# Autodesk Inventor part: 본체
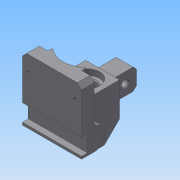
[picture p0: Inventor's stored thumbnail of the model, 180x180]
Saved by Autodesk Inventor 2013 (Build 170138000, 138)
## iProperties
Created: 2016-11
Part Number: 본체
Material: 일반
Document SubType Name: Modeling
Designer: Administrator
Density: 1 g/cm^3
Author: Administrator
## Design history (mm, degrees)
sketch "스케치4"
  geometry: L1 (18, -11)-(0, -29); L2 (0, -29)-(-26, -29); L3 (-30, -25)-(-30, 29); L4 (-30, 29)-(18, 29); L5 (18, 29)-(18, -11); L6 (0, -29)-(0, 29); L7 (-26, -29)-(-30, -25); 3 further points
  constraints: 14 end point, 3 point on line, 2 vertical, 1 coincident, 1 horizontal, 1 midpoint, 1 parallel, 1 perpendicular
  dimensions: "d4" = 45 deg angle of L2 L1; "d5" = 58 distance between parallel lines of L2 L4; "d6" = 48 distance between parallel lines of L3 L5; "d8" = 30 distance from line of L3 L1.end; "d9" = 4 distance of L2.end point (-30, -29); "d10" = 4 distance of L3.start point (-30, -29) (= d9)
extrude "돌출1" new body sketch "스케치4" stored distance "d11" = 40; taper "d12" = 0 deg
sketch "스케치5"
  geometry: L1 (18, 29)-(18, -11) reference; L2 (18, -11)-(0, -29) reference; L3 (0, -29)-(-26, -29) reference; L4 (-26, -29)-(-30, -25) reference; L5 (-30, -25)-(-30, 29) reference; L6 (-30, 29)-(18, 29) reference; L7 (-27, -15)-(-42, -15); L8 (-42, 61)-(-27, 61); L9 (-27, 15.292)-(-27, 61); L10 (-35, -12)-(-42, -12); L11 (-35, -12)-(-35, 8); L12 (-35, 8)-(-42, 8); L13 (-42, -15)-(-42, -12); L14 (-42, 8)-(-42, 61); A1 r 13 centre (-27, -2) between (-27, -15) and (-23.389, 10.488); A2 r 5 centre (-22, 15.292) between (-27, 15.292) and (-23.389, 10.488); 2 further points
  constraints: 16 end point, 5 point on circle, 4 perpendicular, 3 point on line, 3 tangent, 2 centre point, 2 parallel, 1 horizontal
  dimensions: "d19" = 90 distance between parallel lines of L8 L3; "d21" = 26 diameter of A1; "d22" = 63 distance from line of L8 A1.centre; "d23" = 3 distance between parallel lines of L7 L10; "d25" = 20 distance of L10.start L11.end; "d26" = 60 distance between parallel lines of L1 L14; "d27" = 15 distance between parallel lines of L14 L9; "d28" = 7 distance between parallel lines of L13 L11; "d29" = 5 radius of A2
extrude "돌출2" join sketch "스케치5" stored distance "d30" = 70; taper "d31" = 0 deg
sketch "스케치6"
  geometry: L1 (0, -45)-(40, -45) reference; L2 (0, -45)-(0, 0) reference; L3 (0, -40)-(40, -40); L4 (40, -40)-(40, -45); L5 (40, -45)-(0, -45); L6 (0, -45)-(0, -40); 2 further points
  constraints: 8 end point, 2 midpoint, 2 parallel, 1 collinear, 1 horizontal, 1 perpendicular
  dimensions: "d32" = 5 distance of L5.end L3.start
extrude "돌출3" join sketch "스케치6" stored distance "d34" = 10; taper "d35" = 0 deg
sketch "스케치7"
  geometry: L1 (0, 0)-(70, 0) reference; L2 (0, 0)-(0, 15) reference; L3 (0, 15)-(15, 15) reference; L4 (15, 15)-(15, 20) reference; L5 (15, 20)-(55, 20) reference; L6 (55, 20)-(55, 15) reference; L7 (55, 15)-(70, 15) reference; L8 (70, 15)-(70, 0) reference; L9 (70, 0)-(0, 0) reference; C1 r 29 at (35, 42); 2 further points
  constraints: 1 centre point, 1 midpoint, 1 vertical alignment
  dimensions: "d36" = 58 diameter of C1; "d37" = 42 distance from line of L1 C1.centre
extrude "돌출4" cut sketch "스케치7" distance "d38" = 18; taper "d39" = 0 deg
sketch "스케치8"
  geometry: L1 (0, -29)-(-26, -29) reference; L2 (-26, -29)-(-30, -25) reference; L3 (-30, -25)-(-30, -15) reference; L4 (-30, -15)-(-42, -15) reference; L5 (-42, -15)-(-42, -12) reference; L6 (-42, -12)-(-35, -12) reference; L7 (-35, -12)-(-35, 8) reference; L8 (-35, 8)-(-42, 8) reference; L9 (-42, 8)-(-42, 61) reference; L10 (-42, 61)-(-29, 61) reference; L11 (-29, 61)-(-29, 43) reference; L12 (-29, 43)-(-22, 43) reference; L13 (-22, 43)-(-22, 29) reference; L14 (-22, 29)-(18, 29) reference; L15 (18, 29)-(18, -11) reference; L16 (18, -11)-(0, -29) reference; L17 (18, 24)-(44, 24); L18 (48, 20)-(48, 3); L19 (44, -1)-(18, -1); L20 (44, 24)-(48, 20); L21 (48, 3)-(44, -1); 3 further points
  constraints: 10 end point, 6 point on line, 1 horizontal, 1 parallel, 1 perpendicular
  dimensions: "d40" = 25 distance between parallel lines of L19 L17; "d42" = 5 distance between parallel lines of L17 L14; "d43" = 4 distance of L17.end point (48, 24); "d44" = 4 distance of L18.start point (48, 24) (= d43); "d45" = 4 distance of L18.end point (48, -1) (= d43); "d46" = 4 distance of L19.start point (48, -1) (= d45); "d47" = 90 distance between parallel lines of L18 L9
extrude "돌출5" join sketch "스케치8" stored distance "d48" = 20; taper "d49" = 0 deg
sketch "스케치9"
  geometry: L1 (-24, 44)-(-24, 18) reference; L2 (-61, -42)-(-8, -42) reference; 2 further points
  dimensions: "d50" = 12.5 distance from line of point (-11.5, 35) L1; "d51" = 77 distance from line of L2 point (-11.5, 35)
hole "구멍1" sketch "스케치9" at (-11.5, 35) diameter "d52" = 8; stored, may be unused: countersink angle "d56" = 90 deg, drill point angle "d58" = 118 deg; dims "d53" = 6, "d54" = 4, "d55" = 2, "d57" = 8
sketch "스케치12"
  geometry: 2 further points
  constraints: 1 coincident
hole "구멍2" sketch "스케치12" at (20, -18) diameter "d60" = 20; stored, may be unused: countersink angle "d64" = 90 deg, drill point angle "d66" = 118 deg; dims "d61" = 6, "d62" = 29, "d63" = 7, "d65" = 8
chamfer "모따기1" distance "d67" = 1; stored, may be unused: second distance "d68" = 2, angle "d69" = 45 deg
sketch "스케치13"
  geometry: L1 (0, 0)-(15, 0) reference; L2 (15, 45.708)-(15, 0) reference; L3 (15, 0)-(0, 0) reference; L4 (0, 0)-(-9.417, 0) reference; L5 (-9.417, 0)-(-9.417, 18) reference; L6 (-9.417, 18)-(-30.583, 18) reference; L7 (-30.583, 18)-(-30.583, 0) reference; L8 (-30.583, 0)-(-40, 0) reference; L9 (-40, 0)-(-55, 0) reference; L10 (-55, 0)-(-55, 45.708) reference; L11 (-55, 45.708)-(-55, 76) reference; L12 (-55, 76)-(-40, 76) reference; L13 (-40, 76)-(-40, 89) reference; L14 (-40, 89)-(0, 89) reference; L15 (0, 89)-(0, 76) reference; L16 (0, 76)-(15, 76) reference; L17 (15, 76)-(15, 45.708) reference; L18 (15, 45.708)-(15, 0) reference; L19 (0, 45.708)-(0, 0) reference; L20 (15, 45.708)-(0, 45.708) reference; L21 (-40, 0)-(-40, 45.708) reference; L22 (-40, 45.708)-(-55, 45.708) reference; 3 further points
  dimensions: "d70" = 18 distance from line of L1 point (7.5, 18); "d71" = 18 distance from line of L9 point (-47.5, 18); "d76" = 7.5 distance from line of L10 point (-47.5, 18); "d77" = 7.5 distance from line of L2 point (7.5, 18)
hole "구멍3" sketch "스케치13" at (7.5, 18), (-47.5, 18) diameter "d78" = 3.242; stored, may be unused: countersink angle "d82" = 90 deg, drill point angle "d84" = 118 deg; dims "d79" = 6, "d80" = 29, "d81" = 7, "d83" = 8
chamfer "모따기2" distance "d85" = 5; stored, may be unused: second distance "d86" = 2, angle "d87" = 45 deg
fillet "모깎기1" dims "d88" = 3
node "솔리드1"
node "절단 모서리 투영1"
node "절단 모서리 투영2"
node "절단 모서리 투영3"
node "절단 모서리 투영5"
other parameters: "d14" = 15
